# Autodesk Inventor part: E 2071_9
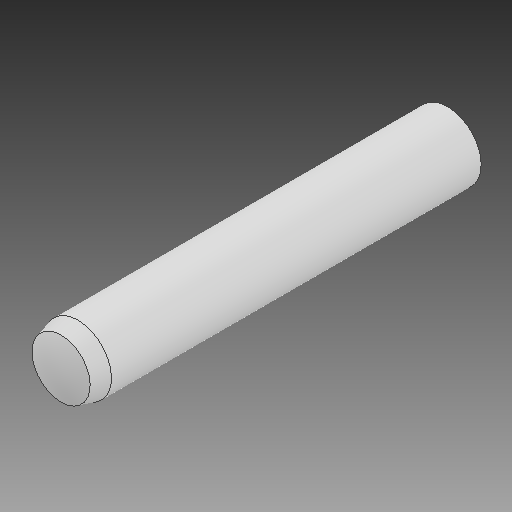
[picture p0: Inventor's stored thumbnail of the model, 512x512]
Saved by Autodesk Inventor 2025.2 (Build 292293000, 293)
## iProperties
Created: 2025-04
Part Number: E 2071_9
Material: Všeobecné
Document SubType Name: Modeling
Designer: Patrik
Density: 1 g/cm^3
Appearance: Výchozí
Mass: 0.989616 g
Surface Area: 7.02502 cm^2
Volume: 0.989616 cm^3
Author: Patrik
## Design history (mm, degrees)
feature "Base1"
node "Těleso1"
